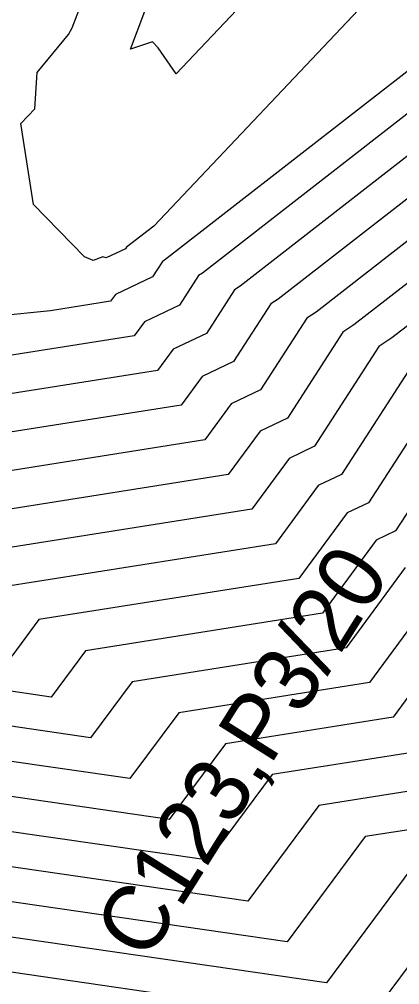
# Model space of a CAD drawing. Extents: x -549394 to -546608, y -1037055 to -1033629.
# Drawn here: x -548898.8 to -548837.4, y -1034470 to -1034314.2 of the extents above; entities that cross this region are included whole.
import ezdxf

# ---------------------------------------------------------------- set-up
doc = ezdxf.new("R2010")
doc.units = 0
for name, color, linetype in [('hlavni_vrst', 7, 'Continuous'), ('norm_vrst', 7, 'Continuous'), ('x_popis_velky_C123', 7, 'Continuous')]:
    doc.layers.add(name, color=color, linetype=linetype)

msp = doc.modelspace()

# ---------------------------------------------------------------- linework, layer by layer
at = {"layer": 'hlavni_vrst'}
for p, q in [((-548827.23, -1034315.61), (-548875.4, -1034353.08)), ((-548791.42, -1034322), (-548844.83, -1034363.54)), ((-548875.73, -1034353.29), (-548877.34, -1034355.79)), ((-548875.4, -1034353.08), (-548875.73, -1034353.29)), ((-548877.34, -1034355.79), (-548883.32, -1034358.63)), ((-548883.32, -1034358.63), (-548884.11, -1034359.7)), ((-548884.11, -1034359.7), (-548893.78, -1034361.24)), ((-548893.78, -1034361.24), (-548909.51, -1034362.87)), ((-548846.62, -1034364.71), (-548855.54, -1034378.56)), ((-548844.83, -1034363.54), (-548846.62, -1034364.71)), ((-548855.54, -1034378.56), (-548859.96, -1034380.65)), ((-548859.96, -1034380.65), (-548865.11, -1034387.66)), ((-548865.11, -1034387.66), (-548918.22, -1034396.08)), ((-548836.59, -1034402.68), (-548846.11, -1034415.62)), ((-548846.11, -1034415.62), (-548880.61, -1034421.09)), ((-548880.61, -1034421.09), (-548887.34, -1034430.14)), ((-548887.34, -1034430.14), (-548933.84, -1034423.41)), ((-548827.11, -1034443.57), (-548843, -1034446.09)), ((-548843, -1034446.09), (-548855.62, -1034463.08)), ((-548855.62, -1034463.08), (-548942.84, -1034450.45))]:
    msp.add_line(p, q, dxfattribs=at)
at = {"layer": 'norm_vrst'}
for p, q in [((-548890.28, -1034315.6), (-548884.61, -1034300.78)), ((-548832.35, -1034300.26), (-548877.14, -1034347.58)), ((-548852.99, -1034301.31), (-548873.52, -1034323.01)), ((-548799.8, -1034301.11), (-548869.29, -1034355.17)), ((-548797.7, -1034306.33), (-548863.17, -1034357.27)), ((-548795.61, -1034311.56), (-548857.06, -1034359.36)), ((-548880.89, -1034319.06), (-548878.58, -1034312.93)), ((-548890.89, -1034316.7), (-548890.28, -1034315.6)), ((-548895.92, -1034322.78), (-548890.89, -1034316.7)), ((-548877.34, -1034317.84), (-548880.89, -1034319.06)), ((-548876.4, -1034318.81), (-548877.34, -1034317.84)), ((-548793.52, -1034316.78), (-548850.94, -1034361.45)), ((-548873.52, -1034323.01), (-548876.4, -1034318.81)), ((-548896.31, -1034328.69), (-548895.92, -1034322.78)), ((-548789.33, -1034327.22), (-548838.71, -1034365.64)), ((-548898.6, -1034331.03), (-548896.31, -1034328.69)), ((-548896.52, -1034344.11), (-548898.6, -1034331.03)), ((-548888.3, -1034352.54), (-548896.52, -1034344.11)), ((-548877.14, -1034347.58), (-548881.52, -1034350.99)), ((-548881.69, -1034351.24), (-548884.83, -1034352.73)), ((-548881.55, -1034351.01), (-548881.69, -1034351.24)), ((-548881.52, -1034350.99), (-548881.55, -1034351.01)), ((-548886.88, -1034353.16), (-548888.3, -1034352.54)), ((-548885.35, -1034352.57), (-548886.88, -1034353.16)), ((-548884.83, -1034352.73), (-548885.35, -1034352.57)), ((-548869.29, -1034355.17), (-548869.9, -1034355.58)), ((-548869.9, -1034355.58), (-548872.98, -1034360.34)), ((-548864.08, -1034357.86), (-548868.62, -1034364.9)), ((-548863.17, -1034357.27), (-548864.08, -1034357.86)), ((-548858.26, -1034360.14), (-548864.26, -1034369.45)), ((-548857.06, -1034359.36), (-548858.26, -1034360.14)), ((-548872.98, -1034360.34), (-548878.65, -1034363.04)), ((-548850.94, -1034361.45), (-548852.44, -1034362.43)), ((-548878.65, -1034363.04), (-548880.31, -1034365.29)), ((-548852.44, -1034362.43), (-548859.9, -1034374)), ((-548880.31, -1034365.29), (-548900.72, -1034368.53)), ((-548868.62, -1034364.9), (-548873.98, -1034367.44)), ((-548838.71, -1034365.64), (-548840.79, -1034366.99)), ((-548873.98, -1034367.44), (-548876.51, -1034370.89)), ((-548840.79, -1034366.99), (-548851.18, -1034383.11)), ((-548864.26, -1034369.45), (-548869.31, -1034371.85)), ((-548834.97, -1034369.28), (-548846.83, -1034387.66)), ((-548876.51, -1034370.89), (-548907.66, -1034375.82)), ((-548869.31, -1034371.85), (-548872.71, -1034376.48)), ((-548829.15, -1034371.56), (-548842.47, -1034392.22)), ((-548859.9, -1034374), (-548864.63, -1034376.25)), ((-548823.33, -1034373.85), (-548838.11, -1034396.77)), ((-548872.71, -1034376.48), (-548914.6, -1034383.12)), ((-548864.63, -1034376.25), (-548868.91, -1034382.07)), ((-548868.91, -1034382.07), (-548921.55, -1034390.41)), ((-548851.18, -1034383.11), (-548855.29, -1034385.06)), ((-548855.29, -1034385.06), (-548861.31, -1034393.25)), ((-548846.83, -1034387.66), (-548850.61, -1034389.46)), ((-548850.61, -1034389.46), (-548857.51, -1034398.84)), ((-548842.47, -1034392.22), (-548845.94, -1034393.87)), ((-548861.31, -1034393.25), (-548910.7, -1034401.08)), ((-548845.94, -1034393.87), (-548853.71, -1034404.43)), ((-548838.11, -1034396.77), (-548841.27, -1034398.27)), ((-548857.51, -1034398.84), (-548903.18, -1034406.08)), ((-548841.27, -1034398.27), (-548849.91, -1034410.03)), ((-548853.71, -1034404.43), (-548895.65, -1034411.08)), ((-548831.92, -1034407.08), (-548842.31, -1034421.21)), ((-548849.91, -1034410.03), (-548888.13, -1034416.09)), ((-548895.65, -1034411.08), (-548900.02, -1034416.97)), ((-548827.25, -1034411.48), (-548838.51, -1034426.8)), ((-548888.13, -1034416.09), (-548893.68, -1034423.56)), ((-548893.68, -1034423.56), (-548932.04, -1034418)), ((-548842.31, -1034421.21), (-548873.09, -1034426.09)), ((-548873.09, -1034426.09), (-548880.99, -1034436.73)), ((-548838.51, -1034426.8), (-548865.57, -1034431.09)), ((-548880.99, -1034436.73), (-548935.64, -1034428.82)), ((-548865.57, -1034431.09), (-548874.65, -1034443.32)), ((-548834.71, -1034432.39), (-548858.04, -1034436.09)), ((-548874.65, -1034443.32), (-548937.44, -1034434.22)), ((-548858.04, -1034436.09), (-548868.3, -1034449.91)), ((-548830.91, -1034437.98), (-548850.52, -1034441.09)), ((-548868.3, -1034449.91), (-548939.24, -1034439.63)), ((-548850.52, -1034441.09), (-548861.96, -1034456.49)), ((-548861.96, -1034456.49), (-548941.04, -1034445.04)), ((-548835.48, -1034451.1), (-548849.27, -1034469.67)), ((-548849.27, -1034469.67), (-548944.64, -1034455.86)), ((-548827.96, -1034456.1), (-548842.93, -1034476.26)), ((-548842.93, -1034476.26), (-548946.44, -1034461.26))]:
    msp.add_line(p, q, dxfattribs=at)

# ---------------------------------------------------------------- texts
at = {"layer": 'x_popis_velky_C123'}
msp.add_text('C123,P3/20', height=10.5, rotation=57.88, dxfattribs=at).set_placement((-548878.28, -1034466.49))

doc.saveas('drawing.dxf')
